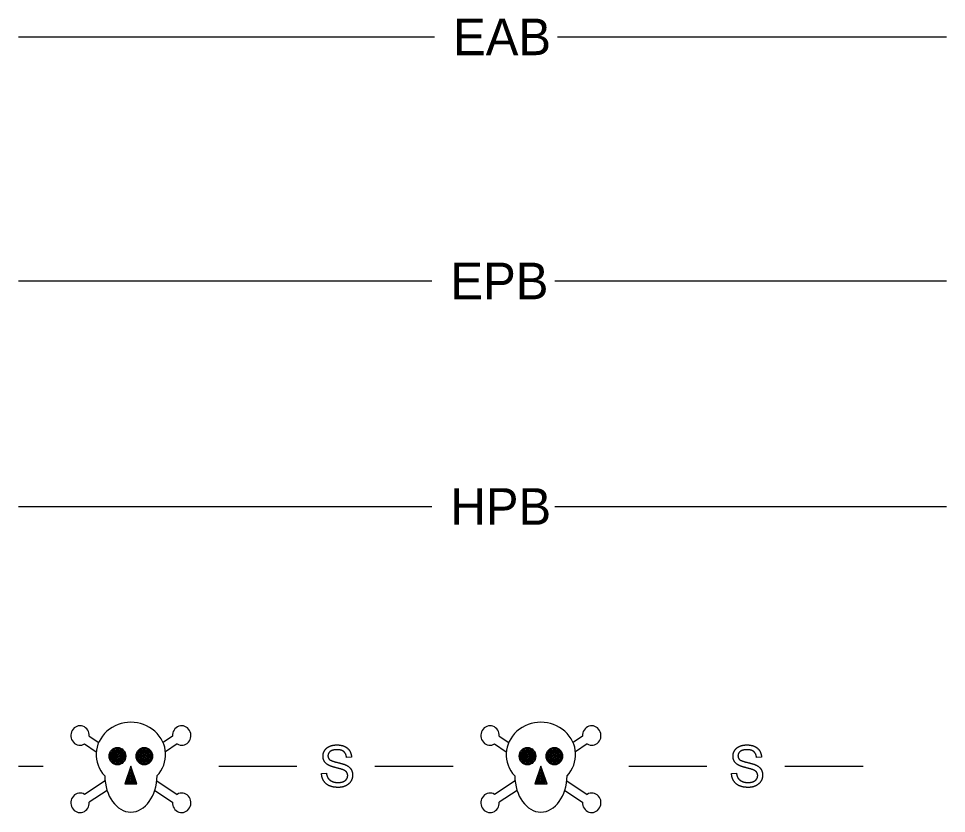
# Model space of a CAD drawing. Extents: x 2025847 to 2026166, y 840763 to 840870.
# Drawn here: x 2026047.68 to 2026054.27, y 840829.79 to 840835.43 of the extents above; entities that cross this region are included whole.
import ezdxf

# ---------------------------------------------------------------- set-up
doc = ezdxf.new("R2010")
doc.units = 0
doc.layers.add('Sheet_Symbology', color=7, linetype='Continuous')

msp = doc.modelspace()

# ---------------------------------------------------------------- linework, layer by layer
at = {"layer": 'Sheet_Symbology'}
for p, q in [((2026047.6824, 840835.2992), (2026050.6345, 840835.2992)), ((2026051.507, 840835.2992), (2026054.2677, 840835.2992)), ((2026047.6824, 840833.5662), (2026050.616, 840833.5662)), ((2026051.4885, 840833.5662), (2026054.2677, 840833.5662)), ((2026047.6824, 840831.9655), (2026050.616, 840831.9655)), ((2026051.4885, 840831.9655), (2026054.2677, 840831.9655)), ((2026048.1841, 840830.3348), (2026048.2513, 840830.2903)), ((2026048.775, 840830.3348), (2026048.7078, 840830.2903)), ((2026051.094, 840830.3348), (2026051.1612, 840830.2903)), ((2026051.6849, 840830.3348), (2026051.6177, 840830.2903)), ((2026048.1512, 840830.2797), (2026048.2342, 840830.2248)), ((2026048.8079, 840830.2797), (2026048.7249, 840830.2248)), ((2026051.0611, 840830.2797), (2026051.1441, 840830.2248)), ((2026051.7178, 840830.2797), (2026051.6348, 840830.2248)), ((2026050.0453, 840830.1859), (2026050.0102, 840830.1831)), ((2026052.9552, 840830.1859), (2026052.9201, 840830.1831)), ((2026047.6824, 840830.1221), (2026047.856, 840830.1221)), ((2026049.1031, 840830.1221), (2026049.6574, 840830.1221)), ((2026050.2116, 840830.1221), (2026050.7659, 840830.1221)), ((2026052.013, 840830.1221), (2026052.5673, 840830.1221)), ((2026053.1215, 840830.1221), (2026053.6758, 840830.1221)), ((2026048.4796, 840830.1009), (2026048.4796, 840830.1009)), ((2026049.8328, 840830.0701), (2026049.8674, 840830.0732)), ((2026051.3895, 840830.1009), (2026051.3895, 840830.1009)), ((2026052.7427, 840830.0701), (2026052.7773, 840830.0732)), ((2026048.2962, 840830.018), (2026048.1512, 840829.9221)), ((2026048.663, 840830.018), (2026048.8079, 840829.9221)), ((2026051.2061, 840830.018), (2026051.0611, 840829.9221)), ((2026051.5729, 840830.018), (2026051.7178, 840829.9221)), ((2026048.3101, 840829.9504), (2026048.1841, 840829.8671)), ((2026048.649, 840829.9504), (2026048.775, 840829.8671)), ((2026051.22, 840829.9504), (2026051.094, 840829.8671)), ((2026051.5589, 840829.9504), (2026051.6849, 840829.8671))]:
    msp.add_line(p, q, dxfattribs=at)
for points in [[(2026048.4796, 840830.1221), (2026048.4361, 840829.9973), (2026048.523, 840829.9973)], [(2026051.3895, 840830.1221), (2026051.346, 840829.9973), (2026051.4329, 840829.9973)], [(2026048.4796, 840830.1009), (2026048.4461, 840830.0046), (2026048.5131, 840830.0046)], [(2026048.4796, 840830.0797), (2026048.456, 840830.0119), (2026048.5032, 840830.0119)], [(2026048.4796, 840830.0585), (2026048.4659, 840830.0192), (2026048.4932, 840830.0192)], [(2026051.3895, 840830.1009), (2026051.356, 840830.0046), (2026051.423, 840830.0046)], [(2026051.3895, 840830.0797), (2026051.3659, 840830.0119), (2026051.413, 840830.0119)], [(2026051.3895, 840830.0585), (2026051.3758, 840830.0192), (2026051.4031, 840830.0192)], [(2026048.4796, 840830.0373), (2026048.4758, 840830.0265), (2026048.4833, 840830.0265)], [(2026051.3895, 840830.0373), (2026051.3857, 840830.0265), (2026051.3932, 840830.0265)]]:
    msp.add_lwpolyline(points, close=True, dxfattribs=at)
for centre, major_axis, ratio, start_param, end_param in [((2026048.4796, 840830.2041), (0.2463, 0), 0.931594, 5.564242, 10.143721), ((2026051.3895, 840830.2041), (0.2463, 0), 0.931594, 5.564242, 10.143721), ((2026048.1186, 840830.3397), (0, 0.0691), 0.95, 4.640789, 9.944994), ((2026048.8405, 840830.3397), (0, 0.0691), 0.95, 2.621377, 7.925582), ((2026051.0285, 840830.3397), (0, 0.0691), 0.95, 4.640789, 9.944994), ((2026051.7504, 840830.3397), (0, 0.0691), 0.95, 2.621377, 7.925582), ((2026048.4796, 840830.0556), (0, -0.2593), 0.714915, 4.722735, 7.843636), ((2026051.3895, 840830.0556), (0, -0.2593), 0.714915, 4.722735, 7.843636), ((2026048.1186, 840829.8621), (0, 0.0691), 0.95, 5.762969, 11.067174), ((2026048.8405, 840829.8621), (0, 0.0691), 0.95, 1.499196, 6.803401), ((2026051.0285, 840829.8621), (0, 0.0691), 0.95, 5.762969, 11.067174), ((2026051.7504, 840829.8621), (0, 0.0691), 0.95, 1.499196, 6.803401)]:
    msp.add_ellipse(centre, major_axis=major_axis, ratio=ratio, start_param=start_param, end_param=end_param, dxfattribs=at)
for centre, major_axis in [((2026048.3841, 840830.1931), (0, 0.0618)), ((2026048.3841, 840830.1931), (0, 0.0545)), ((2026048.575, 840830.1931), (0, 0.0618)), ((2026048.575, 840830.1931), (0, 0.0545)), ((2026051.294, 840830.1931), (0, 0.0618)), ((2026051.294, 840830.1931), (0, 0.0545)), ((2026051.4849, 840830.1931), (0, 0.0618)), ((2026051.4849, 840830.1931), (0, 0.0545)), ((2026048.3841, 840830.1931), (0, 0.0473)), ((2026048.3841, 840830.1931), (0, 0.04)), ((2026048.3841, 840830.1931), (0, 0.0327)), ((2026048.3841, 840830.1931), (0, 0.0254)), ((2026048.3841, 840830.1931), (0, 0.0181)), ((2026048.3841, 840830.1931), (0, 0.0108)), ((2026048.3841, 840830.1931), (0, 0.0035)), ((2026048.575, 840830.1931), (0, 0.0473)), ((2026048.575, 840830.1931), (0, 0.04)), ((2026048.575, 840830.1931), (0, 0.0327)), ((2026048.575, 840830.1931), (0, 0.0254)), ((2026048.575, 840830.1931), (0, 0.0181)), ((2026048.575, 840830.1931), (0, 0.0108)), ((2026048.575, 840830.1931), (0, 0.0035)), ((2026051.294, 840830.1931), (0, 0.0473)), ((2026051.294, 840830.1931), (0, 0.04)), ((2026051.294, 840830.1931), (0, 0.0327)), ((2026051.294, 840830.1931), (0, 0.0254)), ((2026051.294, 840830.1931), (0, 0.0181)), ((2026051.294, 840830.1931), (0, 0.0108)), ((2026051.294, 840830.1931), (0, 0.0035)), ((2026051.4849, 840830.1931), (0, 0.0473)), ((2026051.4849, 840830.1931), (0, 0.04)), ((2026051.4849, 840830.1931), (0, 0.0327)), ((2026051.4849, 840830.1931), (0, 0.0254)), ((2026051.4849, 840830.1931), (0, 0.0181)), ((2026051.4849, 840830.1931), (0, 0.0108)), ((2026051.4849, 840830.1931), (0, 0.0035))]:
    msp.add_ellipse(centre, major_axis=major_axis, ratio=0.95, dxfattribs=at)
for points in [[(2026049.8551, 840830.234), (2026049.867, 840830.2532), (2026049.8899, 840830.2631)], [(2026049.8899, 840830.2631), (2026049.9129, 840830.2731), (2026049.9409, 840830.2731)], [(2026049.9409, 840830.2731), (2026049.9718, 840830.2731), (2026049.9954, 840830.2627)], [(2026049.9954, 840830.2627), (2026050.019, 840830.2522), (2026050.0317, 840830.2319)], [(2026052.765, 840830.234), (2026052.7769, 840830.2532), (2026052.7998, 840830.2631)], [(2026052.7998, 840830.2631), (2026052.8228, 840830.2731), (2026052.8508, 840830.2731)], [(2026052.8508, 840830.2731), (2026052.8817, 840830.2731), (2026052.9053, 840830.2627)], [(2026052.9053, 840830.2627), (2026052.9289, 840830.2522), (2026052.9416, 840830.2319)], [(2026049.8432, 840830.1927), (2026049.8432, 840830.2148), (2026049.8551, 840830.234)], [(2026049.8529, 840830.1563), (2026049.8432, 840830.1725), (2026049.8432, 840830.1927)], [(2026049.8937, 840830.2262), (2026049.8784, 840830.2134), (2026049.8784, 840830.1953)], [(2026049.8784, 840830.1953), (2026049.8784, 840830.1795), (2026049.8893, 840830.1694)], [(2026049.9424, 840830.2391), (2026049.909, 840830.2391), (2026049.8937, 840830.2262)], [(2026049.991, 840830.2249), (2026049.9745, 840830.2391), (2026049.9424, 840830.2391)], [(2026050.0102, 840830.1831), (2026050.0074, 840830.2108), (2026049.991, 840830.2249)], [(2026050.0317, 840830.2319), (2026050.0444, 840830.2116), (2026050.0453, 840830.1859)], [(2026052.753, 840830.1927), (2026052.753, 840830.2148), (2026052.765, 840830.234)], [(2026052.7628, 840830.1563), (2026052.753, 840830.1725), (2026052.753, 840830.1927)], [(2026052.8036, 840830.2262), (2026052.7883, 840830.2134), (2026052.7883, 840830.1953)], [(2026052.7883, 840830.1953), (2026052.7883, 840830.1795), (2026052.7991, 840830.1694)], [(2026052.8523, 840830.2391), (2026052.8189, 840830.2391), (2026052.8036, 840830.2262)], [(2026052.9009, 840830.2249), (2026052.8844, 840830.2391), (2026052.8523, 840830.2391)], [(2026052.9201, 840830.1831), (2026052.9173, 840830.2108), (2026052.9009, 840830.2249)], [(2026052.9416, 840830.2319), (2026052.9542, 840830.2116), (2026052.9552, 840830.1859)], [(2026049.8825, 840830.1291), (2026049.8626, 840830.1401), (2026049.8529, 840830.1563)], [(2026049.9362, 840830.1109), (2026049.8978, 840830.1206), (2026049.8825, 840830.1291)], [(2026049.8893, 840830.1694), (2026049.8999, 840830.1592), (2026049.9448, 840830.1486)], [(2026049.9448, 840830.1486), (2026049.9897, 840830.1379), (2026050.0063, 840830.1299)], [(2026050.0063, 840830.1299), (2026050.0305, 840830.1182), (2026050.042, 840830.1002)], [(2026052.7924, 840830.1291), (2026052.7725, 840830.1401), (2026052.7628, 840830.1563)], [(2026052.8461, 840830.1109), (2026052.8077, 840830.1206), (2026052.7924, 840830.1291)], [(2026052.7991, 840830.1694), (2026052.8098, 840830.1592), (2026052.8547, 840830.1486)], [(2026052.8547, 840830.1486), (2026052.8996, 840830.1379), (2026052.9162, 840830.1299)], [(2026052.9162, 840830.1299), (2026052.9404, 840830.1182), (2026052.9519, 840830.1002)], [(2026049.848, 840830.0177), (2026049.8336, 840830.0408), (2026049.8328, 840830.0701)], [(2026049.8674, 840830.0732), (2026049.8699, 840830.0513), (2026049.8789, 840830.0372)], [(2026049.9857, 840830.0967), (2026049.9745, 840830.1012), (2026049.9362, 840830.1109)], [(2026050.0107, 840830.0794), (2026050.0032, 840830.0897), (2026049.9857, 840830.0967)], [(2026050.0104, 840830.0305), (2026050.0183, 840830.0419), (2026050.0183, 840830.0555)], [(2026050.0183, 840830.0555), (2026050.0183, 840830.0692), (2026050.0107, 840830.0794)], [(2026050.0535, 840830.0587), (2026050.0535, 840830.0354), (2026050.0409, 840830.0148)], [(2026050.042, 840830.1002), (2026050.0535, 840830.0822), (2026050.0535, 840830.0587)], [(2026052.7579, 840830.0177), (2026052.7435, 840830.0408), (2026052.7427, 840830.0701)], [(2026052.7773, 840830.0732), (2026052.7798, 840830.0513), (2026052.7888, 840830.0372)], [(2026052.8956, 840830.0967), (2026052.8844, 840830.1012), (2026052.8461, 840830.1109)], [(2026052.9206, 840830.0794), (2026052.9131, 840830.0897), (2026052.8956, 840830.0967)], [(2026052.9203, 840830.0305), (2026052.9282, 840830.0419), (2026052.9282, 840830.0555)], [(2026052.9282, 840830.0555), (2026052.9282, 840830.0692), (2026052.9206, 840830.0794)], [(2026052.9634, 840830.0587), (2026052.9634, 840830.0354), (2026052.9508, 840830.0148)], [(2026052.9519, 840830.1002), (2026052.9634, 840830.0822), (2026052.9634, 840830.0587)], [(2026049.8879, 840829.9829), (2026049.8625, 840829.9945), (2026049.848, 840830.0177)], [(2026049.8789, 840830.0372), (2026049.8879, 840830.0232), (2026049.9068, 840830.0145)], [(2026049.9068, 840830.0145), (2026049.9257, 840830.0058), (2026049.9494, 840830.0058)], [(2026049.9494, 840830.0058), (2026049.9704, 840830.0058), (2026049.9865, 840830.0124)], [(2026049.9865, 840830.0124), (2026050.0026, 840830.019), (2026050.0104, 840830.0305)], [(2026050.0409, 840830.0148), (2026050.0282, 840829.9943), (2026050.0045, 840829.9828)], [(2026052.7978, 840829.9829), (2026052.7724, 840829.9945), (2026052.7579, 840830.0177)], [(2026052.7888, 840830.0372), (2026052.7978, 840830.0232), (2026052.8167, 840830.0145)], [(2026052.8167, 840830.0145), (2026052.8356, 840830.0058), (2026052.8593, 840830.0058)], [(2026052.8593, 840830.0058), (2026052.8803, 840830.0058), (2026052.8964, 840830.0124)], [(2026052.8964, 840830.0124), (2026052.9124, 840830.019), (2026052.9203, 840830.0305)], [(2026052.9508, 840830.0148), (2026052.9381, 840829.9943), (2026052.9143, 840829.9828)], [(2026049.951, 840829.9714), (2026049.9134, 840829.9714), (2026049.8879, 840829.9829)], [(2026050.0045, 840829.9828), (2026049.9807, 840829.9714), (2026049.951, 840829.9714)], [(2026052.8609, 840829.9714), (2026052.8233, 840829.9714), (2026052.7978, 840829.9829)], [(2026052.9143, 840829.9828), (2026052.8906, 840829.9714), (2026052.8609, 840829.9714)]]:
    msp.add_open_spline(points, degree=2, dxfattribs=at)

# ---------------------------------------------------------------- texts
for s, p in [('EAB', (2026050.7662, 840835.1692)), ('EPB', (2026050.7477, 840833.4362)), ('HPB', (2026050.7477, 840831.8355))]:
    msp.add_text(s, height=0.25995, dxfattribs=at).set_placement(p)

doc.saveas('drawing.dxf')
